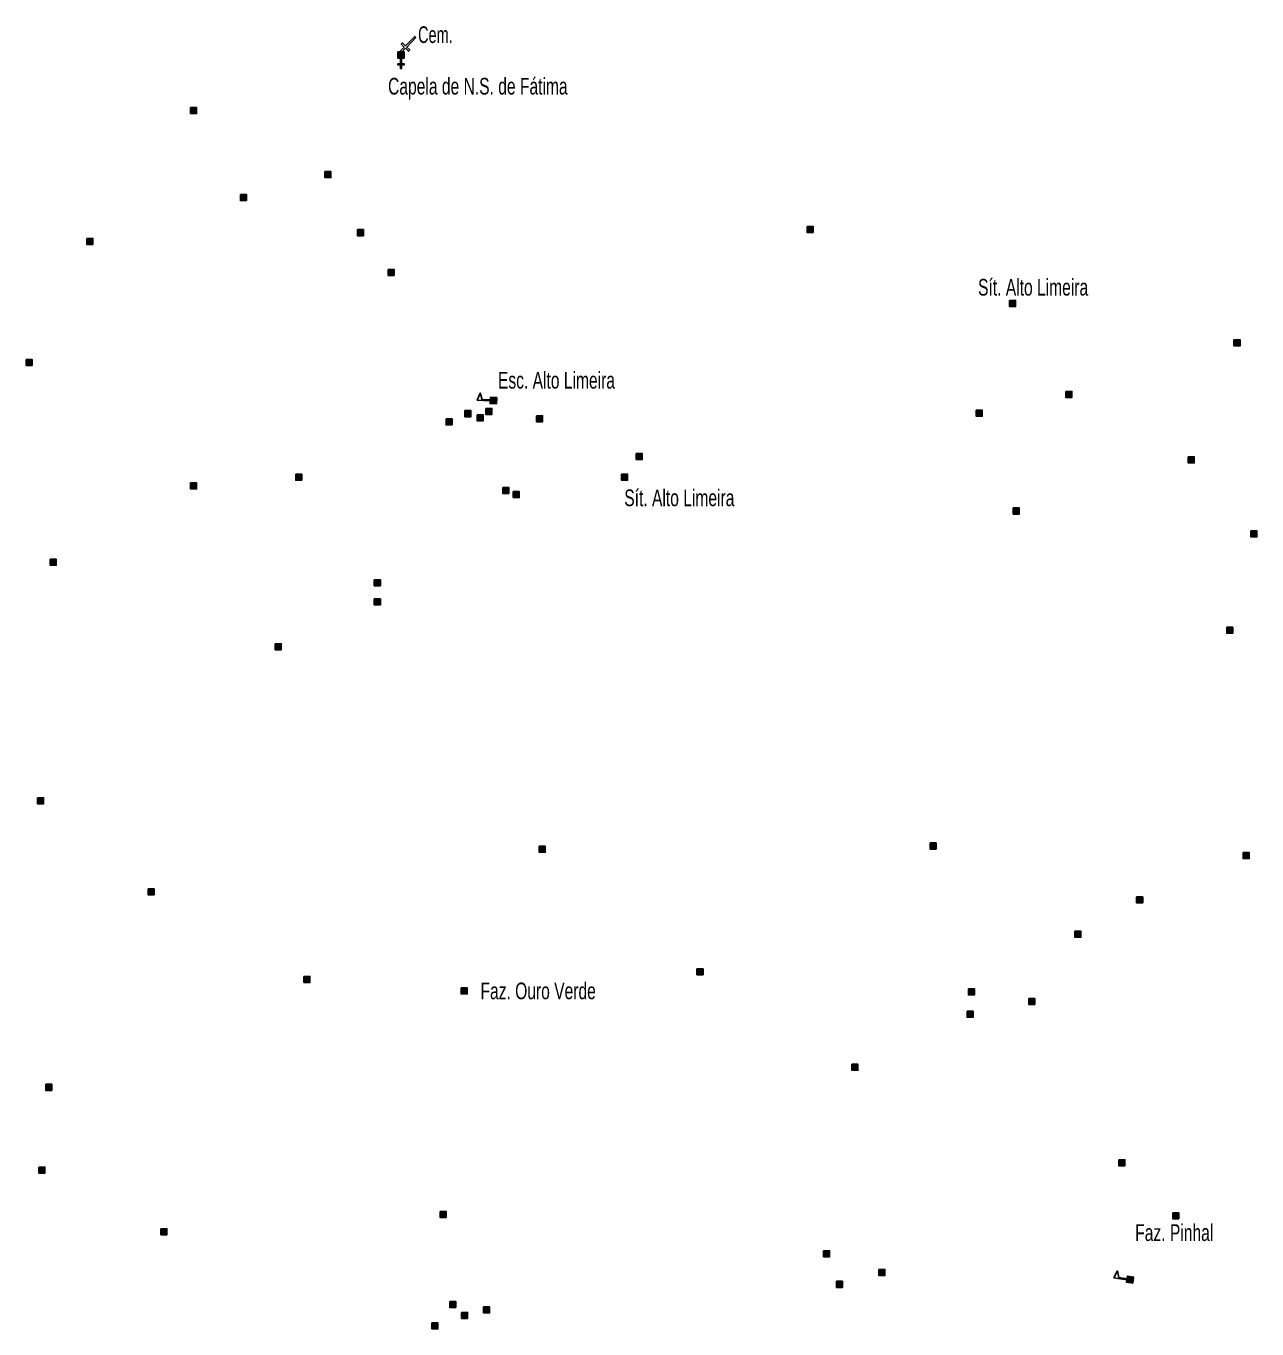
# Model space of a CAD drawing. Extents: x 647.8 to 672.9, y 6929.3 to 6957.3.
# Drawn here: x 648.06 to 653.97, y 6936.48 to 6942.74 of the extents above; entities that cross this region are included whole.
import ezdxf
from ezdxf.enums import TextEntityAlignment as Align

# ---------------------------------------------------------------- set-up
doc = ezdxf.new("R2010")
doc.units = 0
doc.header["$LTSCALE"] = 0.032
for name, color, linetype, lineweight in [('2', 7, 'Continuous', 25), ('20', 7, 'Continuous', 25), ('4', 7, 'Continuous', 25), ('6', 7, 'Continuous', 25)]:
    doc.layers.add(name, color=color, linetype=linetype, lineweight=lineweight)
doc.layers.add('61', color=7, linetype='Continuous')

msp = doc.modelspace()

# ---------------------------------------------------------------- hatches: boundary and pattern name
at = {"layer": '2'}
for points in [[(648.8485, 6942.3449), (648.8775, 6942.3449), (648.8775, 6942.3159), (648.8485, 6942.3159)], [(649.4935, 6942.0377), (649.5225, 6942.0377), (649.5225, 6942.0087), (649.4935, 6942.0087)], [(649.0877, 6941.928), (649.1167, 6941.928), (649.1167, 6941.899), (649.0877, 6941.899)], [(649.6493, 6941.7591), (649.6783, 6941.7591), (649.6783, 6941.7301), (649.6493, 6941.7301)], [(651.808, 6941.7745), (651.837, 6941.7745), (651.837, 6941.7455), (651.808, 6941.7455)], [(648.3505, 6941.7174), (648.3795, 6941.7174), (648.3795, 6941.6884), (648.3505, 6941.6884)], [(649.7963, 6941.5682), (649.8253, 6941.5682), (649.8253, 6941.5392), (649.7963, 6941.5392)], [(652.7799, 6941.4191), (652.8089, 6941.4191), (652.8089, 6941.3901), (652.7799, 6941.3901)], [(653.8571, 6941.2304), (653.8861, 6941.2304), (653.8861, 6941.2014), (653.8571, 6941.2014)], [(648.0588, 6941.1361), (648.0878, 6941.1361), (648.0878, 6941.1071), (648.0588, 6941.1071)], [(653.0498, 6940.9825), (653.0788, 6940.9825), (653.0788, 6940.9535), (653.0498, 6940.9535)], [(650.1649, 6940.8903), (650.1939, 6940.8903), (650.1939, 6940.8613), (650.1649, 6940.8613)], [(650.2241, 6940.8706), (650.2531, 6940.8706), (650.2531, 6940.8416), (650.2241, 6940.8416)], [(650.2658, 6940.9013), (650.2948, 6940.9013), (650.2948, 6940.8723), (650.2658, 6940.8723)], [(652.6198, 6940.8925), (652.6488, 6940.8925), (652.6488, 6940.8635), (652.6198, 6940.8635)], [(650.0749, 6940.8509), (650.1039, 6940.8509), (650.1039, 6940.8219), (650.0749, 6940.8219)], [(650.5093, 6940.8662), (650.5383, 6940.8662), (650.5383, 6940.8372), (650.5093, 6940.8372)], [(650.9875, 6940.6841), (651.0165, 6940.6841), (651.0165, 6940.6551), (650.9875, 6940.6551)], [(653.6377, 6940.6688), (653.6667, 6940.6688), (653.6667, 6940.6398), (653.6377, 6940.6398)], [(649.3531, 6940.5854), (649.3821, 6940.5854), (649.3821, 6940.5564), (649.3531, 6940.5564)], [(650.9173, 6940.5854), (650.9463, 6940.5854), (650.9463, 6940.5564), (650.9173, 6940.5564)], [(648.8485, 6940.5437), (648.8775, 6940.5437), (648.8775, 6940.5147), (648.8485, 6940.5147)], [(650.3469, 6940.5218), (650.3759, 6940.5218), (650.3759, 6940.4928), (650.3469, 6940.4928)], [(650.3974, 6940.502), (650.4264, 6940.502), (650.4264, 6940.473), (650.3974, 6940.473)], [(652.7975, 6940.4231), (652.8265, 6940.4231), (652.8265, 6940.3941), (652.7975, 6940.3941)], [(653.9383, 6940.3134), (653.9673, 6940.3134), (653.9673, 6940.2844), (653.9383, 6940.2844)], [(648.175, 6940.1773), (648.204, 6940.1773), (648.204, 6940.1483), (648.175, 6940.1483)], [(649.7305, 6940.0786), (649.7595, 6940.0786), (649.7595, 6940.0496), (649.7305, 6940.0496)], [(649.7305, 6939.9865), (649.7595, 6939.9865), (649.7595, 6939.9575), (649.7305, 6939.9575)], [(653.822, 6939.8505), (653.851, 6939.8505), (653.851, 6939.8215), (653.822, 6939.8215)], [(649.2544, 6939.7715), (649.2834, 6939.7715), (649.2834, 6939.7425), (649.2544, 6939.7425)], [(648.1136, 6939.0322), (648.1426, 6939.0322), (648.1426, 6939.0032), (648.1136, 6939.0032)], [(652.3982, 6938.815), (652.4272, 6938.815), (652.4272, 6938.786), (652.3982, 6938.786)], [(650.5224, 6938.7996), (650.5514, 6938.7996), (650.5514, 6938.7706), (650.5224, 6938.7706)], [(653.901, 6938.7689), (653.93, 6938.7689), (653.93, 6938.7399), (653.901, 6938.7399)], [(648.6445, 6938.5956), (648.6735, 6938.5956), (648.6735, 6938.5666), (648.6445, 6938.5666)], [(653.3898, 6938.5561), (653.4188, 6938.5561), (653.4188, 6938.5271), (653.3898, 6938.5271)], [(653.0936, 6938.3916), (653.1226, 6938.3916), (653.1226, 6938.3626), (653.0936, 6938.3626)], [(651.2793, 6938.2117), (651.3083, 6938.2117), (651.3083, 6938.1827), (651.2793, 6938.1827)], [(649.3926, 6938.1744), (649.4216, 6938.1744), (649.4216, 6938.1454), (649.3926, 6938.1454)], [(650.1473, 6938.1195), (650.1763, 6938.1195), (650.1763, 6938.0905), (650.1473, 6938.0905)], [(652.5825, 6938.1151), (652.6115, 6938.1151), (652.6115, 6938.0861), (652.5825, 6938.0861)], [(652.8721, 6938.0691), (652.9011, 6938.0691), (652.9011, 6938.0401), (652.8721, 6938.0401)], [(652.5759, 6938.0076), (652.6049, 6938.0076), (652.6049, 6937.9786), (652.5759, 6937.9786)], [(652.023, 6937.7531), (652.052, 6937.7531), (652.052, 6937.7241), (652.023, 6937.7241)], [(648.1531, 6937.6566), (648.1821, 6937.6566), (648.1821, 6937.6276), (648.1531, 6937.6276)], [(648.1202, 6937.2595), (648.1492, 6937.2595), (648.1492, 6937.2305), (648.1202, 6937.2305)], [(653.3042, 6937.2946), (653.3332, 6937.2946), (653.3332, 6937.2656), (653.3042, 6937.2656)], [(650.0464, 6937.0467), (650.0754, 6937.0467), (650.0754, 6937.0177), (650.0464, 6937.0177)], [(653.5631, 6937.0401), (653.5921, 6937.0401), (653.5921, 6937.0111), (653.5631, 6937.0111)], [(648.7059, 6936.9634), (648.7349, 6936.9634), (648.7349, 6936.9344), (648.7059, 6936.9344)], [(651.887, 6936.8581), (651.916, 6936.8581), (651.916, 6936.8291), (651.887, 6936.8291)], [(652.1525, 6936.7681), (652.1815, 6936.7681), (652.1815, 6936.7391), (652.1525, 6936.7391)], [(651.9484, 6936.7111), (651.9774, 6936.7111), (651.9774, 6936.6821), (651.9484, 6936.6821)], [(650.0925, 6936.6145), (650.1215, 6936.6145), (650.1215, 6936.5855), (650.0925, 6936.5855)], [(650.1495, 6936.5619), (650.1785, 6936.5619), (650.1785, 6936.5329), (650.1495, 6936.5329)], [(650.2548, 6936.5882), (650.2838, 6936.5882), (650.2838, 6936.5592), (650.2548, 6936.5592)], [(650.0069, 6936.5114), (650.0359, 6936.5114), (650.0359, 6936.4824), (650.0069, 6936.4824)]]:
    msp.add_hatch(color=256, dxfattribs=at).paths.add_polyline_path(points)
at = {"layer": '4'}
for points in [[(650.3166, 6940.9232), (650.2866, 6940.9246), (650.288, 6940.9546), (650.318, 6940.9532)], [(653.3708, 6936.7019), (653.3411, 6936.7063), (653.3455, 6936.736), (653.3752, 6936.7316)]]:
    msp.add_hatch(color=256, dxfattribs=at).paths.add_polyline_path(points)
at = {"layer": '6'}
for points in [[(649.8565, 6942.5824), (649.8615, 6942.5824), (649.8613, 6942.5549), (649.8739, 6942.5547), (649.8738, 6942.5497), (649.8613, 6942.5499), (649.8612, 6942.5324), (649.8562, 6942.5324), (649.8563, 6942.5499), (649.8438, 6942.5499), (649.8438, 6942.5549), (649.8563, 6942.5549)], [(649.874, 6942.5823), (649.8742, 6942.6123), (649.8442, 6942.6125), (649.844, 6942.5825)]]:
    msp.add_hatch(color=256, dxfattribs=at).paths.add_polyline_path(points)

# ---------------------------------------------------------------- linework, layer by layer
at = {"layer": '2'}
for points in [[(648.8485, 6942.3449), (648.8775, 6942.3449), (648.8775, 6942.3159), (648.8485, 6942.3159)], [(649.4935, 6942.0377), (649.5225, 6942.0377), (649.5225, 6942.0087), (649.4935, 6942.0087)], [(649.0877, 6941.928), (649.1167, 6941.928), (649.1167, 6941.899), (649.0877, 6941.899)], [(649.6493, 6941.7591), (649.6783, 6941.7591), (649.6783, 6941.7301), (649.6493, 6941.7301)], [(651.808, 6941.7745), (651.837, 6941.7745), (651.837, 6941.7455), (651.808, 6941.7455)], [(648.3505, 6941.7174), (648.3795, 6941.7174), (648.3795, 6941.6884), (648.3505, 6941.6884)], [(649.7963, 6941.5682), (649.8253, 6941.5682), (649.8253, 6941.5392), (649.7963, 6941.5392)], [(652.7799, 6941.4191), (652.8089, 6941.4191), (652.8089, 6941.3901), (652.7799, 6941.3901)], [(653.8571, 6941.2304), (653.8861, 6941.2304), (653.8861, 6941.2014), (653.8571, 6941.2014)], [(648.0588, 6941.1361), (648.0878, 6941.1361), (648.0878, 6941.1071), (648.0588, 6941.1071)], [(653.0498, 6940.9825), (653.0788, 6940.9825), (653.0788, 6940.9535), (653.0498, 6940.9535)], [(650.1649, 6940.8903), (650.1939, 6940.8903), (650.1939, 6940.8613), (650.1649, 6940.8613)], [(650.2241, 6940.8706), (650.2531, 6940.8706), (650.2531, 6940.8416), (650.2241, 6940.8416)], [(650.2658, 6940.9013), (650.2948, 6940.9013), (650.2948, 6940.8723), (650.2658, 6940.8723)], [(652.6198, 6940.8925), (652.6488, 6940.8925), (652.6488, 6940.8635), (652.6198, 6940.8635)], [(650.0749, 6940.8509), (650.1039, 6940.8509), (650.1039, 6940.8219), (650.0749, 6940.8219)], [(650.5093, 6940.8662), (650.5383, 6940.8662), (650.5383, 6940.8372), (650.5093, 6940.8372)], [(650.9875, 6940.6841), (651.0165, 6940.6841), (651.0165, 6940.6551), (650.9875, 6940.6551)], [(653.6377, 6940.6688), (653.6667, 6940.6688), (653.6667, 6940.6398), (653.6377, 6940.6398)], [(649.3531, 6940.5854), (649.3821, 6940.5854), (649.3821, 6940.5564), (649.3531, 6940.5564)], [(650.9173, 6940.5854), (650.9463, 6940.5854), (650.9463, 6940.5564), (650.9173, 6940.5564)], [(648.8485, 6940.5437), (648.8775, 6940.5437), (648.8775, 6940.5147), (648.8485, 6940.5147)], [(650.3469, 6940.5218), (650.3759, 6940.5218), (650.3759, 6940.4928), (650.3469, 6940.4928)], [(650.3974, 6940.502), (650.4264, 6940.502), (650.4264, 6940.473), (650.3974, 6940.473)], [(652.7975, 6940.4231), (652.8265, 6940.4231), (652.8265, 6940.3941), (652.7975, 6940.3941)], [(653.9383, 6940.3134), (653.9673, 6940.3134), (653.9673, 6940.2844), (653.9383, 6940.2844)], [(648.175, 6940.1773), (648.204, 6940.1773), (648.204, 6940.1483), (648.175, 6940.1483)], [(649.7305, 6940.0786), (649.7595, 6940.0786), (649.7595, 6940.0496), (649.7305, 6940.0496)], [(649.7305, 6939.9865), (649.7595, 6939.9865), (649.7595, 6939.9575), (649.7305, 6939.9575)], [(653.822, 6939.8505), (653.851, 6939.8505), (653.851, 6939.8215), (653.822, 6939.8215)], [(649.2544, 6939.7715), (649.2834, 6939.7715), (649.2834, 6939.7425), (649.2544, 6939.7425)], [(648.1136, 6939.0322), (648.1426, 6939.0322), (648.1426, 6939.0032), (648.1136, 6939.0032)], [(652.3982, 6938.815), (652.4272, 6938.815), (652.4272, 6938.786), (652.3982, 6938.786)], [(650.5224, 6938.7996), (650.5514, 6938.7996), (650.5514, 6938.7706), (650.5224, 6938.7706)], [(653.901, 6938.7689), (653.93, 6938.7689), (653.93, 6938.7399), (653.901, 6938.7399)], [(648.6445, 6938.5956), (648.6735, 6938.5956), (648.6735, 6938.5666), (648.6445, 6938.5666)], [(653.3898, 6938.5561), (653.4188, 6938.5561), (653.4188, 6938.5271), (653.3898, 6938.5271)], [(653.0936, 6938.3916), (653.1226, 6938.3916), (653.1226, 6938.3626), (653.0936, 6938.3626)], [(651.2793, 6938.2117), (651.3083, 6938.2117), (651.3083, 6938.1827), (651.2793, 6938.1827)], [(649.3926, 6938.1744), (649.4216, 6938.1744), (649.4216, 6938.1454), (649.3926, 6938.1454)], [(650.1473, 6938.1195), (650.1763, 6938.1195), (650.1763, 6938.0905), (650.1473, 6938.0905)], [(652.5825, 6938.1151), (652.6115, 6938.1151), (652.6115, 6938.0861), (652.5825, 6938.0861)], [(652.8721, 6938.0691), (652.9011, 6938.0691), (652.9011, 6938.0401), (652.8721, 6938.0401)], [(652.5759, 6938.0076), (652.6049, 6938.0076), (652.6049, 6937.9786), (652.5759, 6937.9786)], [(652.023, 6937.7531), (652.052, 6937.7531), (652.052, 6937.7241), (652.023, 6937.7241)], [(648.1531, 6937.6566), (648.1821, 6937.6566), (648.1821, 6937.6276), (648.1531, 6937.6276)], [(648.1202, 6937.2595), (648.1492, 6937.2595), (648.1492, 6937.2305), (648.1202, 6937.2305)], [(653.3042, 6937.2946), (653.3332, 6937.2946), (653.3332, 6937.2656), (653.3042, 6937.2656)], [(650.0464, 6937.0467), (650.0754, 6937.0467), (650.0754, 6937.0177), (650.0464, 6937.0177)], [(653.5631, 6937.0401), (653.5921, 6937.0401), (653.5921, 6937.0111), (653.5631, 6937.0111)], [(648.7059, 6936.9634), (648.7349, 6936.9634), (648.7349, 6936.9344), (648.7059, 6936.9344)], [(651.887, 6936.8581), (651.916, 6936.8581), (651.916, 6936.8291), (651.887, 6936.8291)], [(652.1525, 6936.7681), (652.1815, 6936.7681), (652.1815, 6936.7391), (652.1525, 6936.7391)], [(651.9484, 6936.7111), (651.9774, 6936.7111), (651.9774, 6936.6821), (651.9484, 6936.6821)], [(650.0925, 6936.6145), (650.1215, 6936.6145), (650.1215, 6936.5855), (650.0925, 6936.5855)], [(650.1495, 6936.5619), (650.1785, 6936.5619), (650.1785, 6936.5329), (650.1495, 6936.5329)], [(650.2548, 6936.5882), (650.2838, 6936.5882), (650.2838, 6936.5592), (650.2548, 6936.5592)], [(650.0069, 6936.5114), (650.0359, 6936.5114), (650.0359, 6936.4824), (650.0069, 6936.4824)]]:
    msp.add_lwpolyline(points, close=True, dxfattribs=at)
at = {"layer": '20'}
for points in [[(649.9302, 6942.6813), (649.9244, 6942.6869), (649.8802, 6942.6413)], [(649.8744, 6942.6352), (649.8548, 6942.6151), (649.8606, 6942.6095), (649.88, 6942.6296)], [(649.8802, 6942.6413), (649.866, 6942.6552), (649.86, 6942.6491), (649.8744, 6942.6352)], [(649.88, 6942.6296), (649.8944, 6942.6157), (649.9004, 6942.6218), (649.886, 6942.6357), (649.9302, 6942.6813)]]:
    msp.add_lwpolyline(points, dxfattribs=at)
at = {"layer": '4'}
for p, q in [((650.2872, 6940.9371), (650.2874, 6940.9421)), ((653.343, 6936.7187), (653.3437, 6936.7236))]:
    msp.add_line(p, q, dxfattribs=at)
for points in [[(650.2872, 6940.9371), (650.2247, 6940.94), (650.2389, 6940.9744), (650.248, 6940.9439), (650.2874, 6940.9421)], [(650.3166, 6940.9232), (650.2866, 6940.9246), (650.288, 6940.9546), (650.318, 6940.9532)], [(653.343, 6936.7187), (653.2811, 6936.7279), (653.2986, 6936.7606), (653.3046, 6936.7294), (653.3437, 6936.7236)], [(653.3708, 6936.7019), (653.3411, 6936.7063), (653.3455, 6936.736), (653.3752, 6936.7316)]]:
    msp.add_lwpolyline(points, close=True, dxfattribs=at)
at = {"layer": '6'}
for points in [[(649.8565, 6942.5824), (649.8615, 6942.5824), (649.8613, 6942.5549), (649.8739, 6942.5547), (649.8738, 6942.5497), (649.8613, 6942.5499), (649.8612, 6942.5324), (649.8562, 6942.5324), (649.8563, 6942.5499), (649.8438, 6942.5499), (649.8438, 6942.5549), (649.8563, 6942.5549)], [(649.874, 6942.5823), (649.8742, 6942.6123), (649.8442, 6942.6125), (649.844, 6942.5825)]]:
    msp.add_lwpolyline(points, close=True, dxfattribs=at)

# ---------------------------------------------------------------- texts
at = {"layer": '61'}
for s, width, p in [('Cem.', 0.65, (649.9406, 6942.6552)), ('Capela de N.S. de Fátima', 0.7, (649.7967, 6942.4078)), ('Sít. Alto Limeira', 0.7, (652.6286, 6941.4427)), ('Esc. Alto Limeira', 0.7, (650.324, 6940.9963)), ('Sít. Alto Limeira', 0.7, (650.9304, 6940.4318)), ('Faz. Ouro Verde', 0.7, (650.2402, 6938.0651))]:
    msp.add_text(s, height=0.08, dxfattribs=dict(at, width=width)).set_placement(p)
at = {"layer": '61', "width": 0.7}
msp.add_text('Faz. Pinhal', height=0.08, dxfattribs=at).set_placement((653.7576, 6936.9046), align=Align.RIGHT)

doc.saveas('drawing.dxf')
